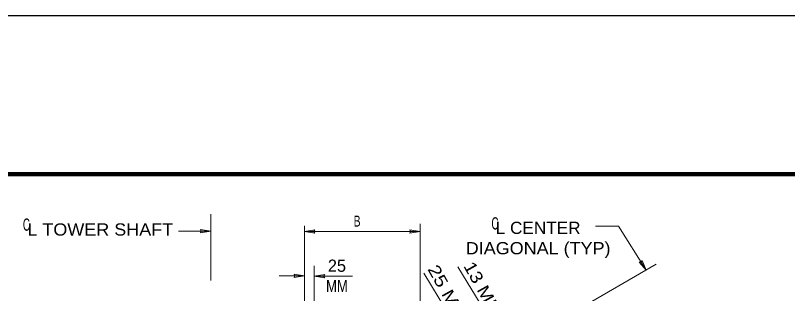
# Model space of a CAD drawing. Extents: x 312601.858 to 312602.699, y 144420.109 to 144420.704.
# Drawn here: x 312602.2782 to 312602.4677, y 144420.6351 to 144420.7035 of the extents above; entities that cross this region are included whole.
import ezdxf
from ezdxf.enums import TextEntityAlignment as Align

# ---------------------------------------------------------------- set-up
doc = ezdxf.new("R2010")
doc.units = 0
doc.header["$LTSCALE"] = 0.0012
for name, color, linetype, lineweight in [('1', 7, 'Continuous', 25), ('2', 7, 'Continuous', 13), ('39', 7, 'Continuous', 13)]:
    doc.layers.add(name, color=color, linetype=linetype, lineweight=lineweight)

msp = doc.modelspace()

# ---------------------------------------------------------------- hatches: boundary and pattern name
at = {"layer": '39'}
for points in [[(312602.3238, 144420.6505), (312602.3236, 144420.6509), (312602.3261, 144420.6505), (312602.3236, 144420.6501)], [(312602.3514, 144420.6504), (312602.3517, 144420.65), (312602.3491, 144420.6504), (312602.3517, 144420.6508)], [(312602.3752, 144420.6504), (312602.375, 144420.6508), (312602.3775, 144420.6504), (312602.375, 144420.65)], [(312602.4318, 144420.6429), (312602.432, 144420.6433), (312602.433, 144420.6409), (312602.4313, 144420.6429)], [(312602.3468, 144420.6395), (312602.3466, 144420.6399), (312602.3491, 144420.6395), (312602.3466, 144420.6391)], [(312602.3538, 144420.6394), (312602.3541, 144420.639), (312602.3515, 144420.6394), (312602.3541, 144420.6398)]]:
    msp.add_hatch(color=256, dxfattribs=at).paths.add_polyline_path(points)

# ---------------------------------------------------------------- linework, layer by layer
at = {"layer": '1', "lineweight": 13}
for p, q in [((312602.3261, 144420.6547), (312602.3261, 144420.6384)), ((312602.3491, 144420.6304), (312602.3491, 144420.6518)), ((312602.3775, 144420.6523), (312602.3775, 144420.6201)), ((312602.4206, 144420.6517), (312602.4262, 144420.6517)), ((312602.3491, 144420.6504), (312602.3775, 144420.6504)), ((312602.3515, 144420.642), (312602.3515, 144420.6177)), ((312602.3868, 144420.6417), (312602.3945, 144420.6291)), ((312602.4132, 144420.6295), (312602.4355, 144420.6424)), ((312602.3429, 144420.6395), (312602.3491, 144420.6395)), ((312602.3515, 144420.6394), (312602.3609, 144420.6394)), ((312602.3784, 144420.6402), (312602.386, 144420.6277))]:
    msp.add_line(p, q, dxfattribs=at)
at = {"layer": '2'}
for p, q in [((312602.3182, 144420.6505), (312602.3261, 144420.6505)), ((312602.4262, 144420.6517), (312602.433, 144420.6409))]:
    msp.add_line(p, q, dxfattribs=at)
at = {"layer": '39', "lineweight": 25}
msp.add_line((312601.8578, 144420.7035), (312602.6988, 144420.7035), dxfattribs=at)
at = {"layer": '39', "lineweight": 158}
msp.add_line((312601.9088, 144420.6645), (312602.6838, 144420.6645), dxfattribs=at)
at = {"layer": '39'}
for points in [[(312602.3238, 144420.6505), (312602.3236, 144420.6509), (312602.3261, 144420.6505), (312602.3236, 144420.6501)], [(312602.3514, 144420.6504), (312602.3517, 144420.65), (312602.3491, 144420.6504), (312602.3517, 144420.6508)], [(312602.3752, 144420.6504), (312602.375, 144420.6508), (312602.3775, 144420.6504), (312602.375, 144420.65)], [(312602.4318, 144420.6429), (312602.432, 144420.6433), (312602.433, 144420.6409), (312602.4313, 144420.6429)], [(312602.3468, 144420.6395), (312602.3466, 144420.6399), (312602.3491, 144420.6395), (312602.3466, 144420.6391)], [(312602.3538, 144420.6394), (312602.3541, 144420.639), (312602.3515, 144420.6394), (312602.3541, 144420.6398)]]:
    msp.add_lwpolyline(points, close=True, dxfattribs=at)

# ---------------------------------------------------------------- texts
at = {"layer": '2'}
for s, height, width, p in [('B', 0.0027, 0.7, (312602.36205, 144420.6516)), ('C', 0.003, 0.6, (312602.3959, 144420.6509)), ('L CENTER', 0.003, 1.05, (312602.4065, 144420.6498)), ('DIAGONAL (TYP)', 0.003, 1.1, (312602.4065, 144420.6448)), ('MM', 0.003, 0.8, (312602.3571, 144420.6355))]:
    msp.add_text(s, height=height, dxfattribs=dict(at, width=width)).set_placement(p, align=Align.CENTER)
for s, width, p in [('C', 0.6, (312602.28, 144420.6506)), ('L TOWER SHAFT', 1.1, (312602.2811, 144420.6494))]:
    msp.add_text(s, height=0.003, dxfattribs=dict(at, width=width)).set_placement(p)
msp.add_text('25', height=0.003, dxfattribs=at).set_placement((312602.3571, 144420.6405), align=Align.CENTER)
for s, height, width, p in [('25 MM', 0.002999, 1.25, (312602.382993, 144420.634481)), ('13 MM', 0.003, 1.2, (312602.391653, 144420.635531))]:
    msp.add_text(s, height=height, rotation=299.156, dxfattribs=dict(at, width=width)).set_placement(p, align=Align.CENTER)

doc.saveas('drawing.dxf')
